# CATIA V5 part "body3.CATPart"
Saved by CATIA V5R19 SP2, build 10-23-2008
Part number: body3
Bounding box of the stored display mesh (mm): x -1290.464 to 1901.807, y -751.014 to 751.014, z 24.481 to 1015.966
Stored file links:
  C:\BEHROOZ\catia learning\tarh haye mashin\hb\body3.CATPart
  C:\BEHROOZ\catia learning\tarh haye mashin\hb\HB.CATPart
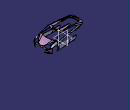
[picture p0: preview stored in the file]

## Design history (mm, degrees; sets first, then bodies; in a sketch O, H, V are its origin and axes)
Body1 (main body)
  Set1
    DatumSurface1
    DatumSurface2
    ThickSurface1: Surface DatumSurface2, TopOffset 1, BotOffset 0
    DatumSurface3 to DatumSurface6
    ThickSurface2: Surface DatumSurface6, TopOffset 1, BotOffset 0
    DatumSurface7 to DatumSurface9
    ThickSurface3: Surface DatumSurface9, TopOffset 1, BotOffset 0
    DatumSurface10 to DatumSurface12
    ThickSurface4: Surface DatumSurface12, TopOffset 1, BotOffset 0
    DatumSurface13
    DatumSurface14
    ThickSurface5: Surface DatumSurface14, TopOffset 1, BotOffset 0
    DatumSurface15
    ThickSurface6: Surface DatumSurface15, TopOffset 1, BotOffset 0
    DatumSurface16
    ThickSurface7: Surface DatumSurface16, TopOffset 1, BotOffset 0
    DatumSurface17
    ThickSurface8: Surface DatumSurface17, TopOffset 1, BotOffset 0
    DatumSurface18
    DatumSurface19
    ThickSurface9: Surface DatumSurface18, TopOffset 1, BotOffset 0
    DatumSurface20 to DatumSurface33
    ThickSurface10: Surface DatumSurface21, TopOffset 1, BotOffset 0
    ThickSurface11: Surface DatumSurface20, TopOffset 1, BotOffset 0
    ThickSurface12: Surface DatumSurface23, TopOffset 1, BotOffset 0
    ThickSurface13: Surface DatumSurface31, TopOffset 1, BotOffset 0
    ThickSurface14: Surface DatumSurface22, TopOffset 1, BotOffset 0
    ThickSurface15: Surface DatumSurface26, TopOffset 1, BotOffset 0
    ThickSurface16: Surface DatumSurface24, TopOffset 1, BotOffset 0
    ThickSurface17: Surface DatumSurface25, TopOffset 1, BotOffset 0
    ThickSurface18: Surface DatumSurface29, TopOffset 1, BotOffset 0
    ThickSurface19: Surface DatumSurface30, TopOffset 1, BotOffset 0
    ThickSurface20: Surface DatumSurface27, TopOffset 1, BotOffset 0
    ThickSurface21: Surface DatumSurface33, TopOffset 1, BotOffset 0
    DatumSurface34
    DatumSurface35
    ThickSurface22: Surface DatumSurface35, TopOffset 1, BotOffset 0
    DatumSurface36
    ThickSurface23: Surface DatumSurface36, TopOffset 1, BotOffset 0
    DatumSurface37
    DatumSurface38
    ThickSurface24: Surface DatumSurface38, TopOffset 1, BotOffset 0
    DatumSurface39 to DatumSurface53
    ThickSurface25: Surface DatumSurface52, TopOffset 1, BotOffset 0
    DatumSurface54
    ThickSurface26: Surface DatumSurface43, TopOffset 1, BotOffset 0
    DatumSurface55
    ThickSurface27: Surface DatumSurface55, TopOffset 1, BotOffset 0
    DatumSurface56
    DatumSurface57
    ThickSurface28: Surface DatumSurface57, TopOffset 1, BotOffset 0
    DatumSurface58
    ThickSurface29: Surface DatumSurface58, TopOffset 1, BotOffset 0
    DatumSurface59
    ThickSurface30: Surface DatumSurface59, TopOffset 1, BotOffset 0
    DatumSurface60
    ThickSurface31: Surface DatumSurface60, TopOffset 1, BotOffset 0
    DatumSurface61
    DatumSurface62
    ThickSurface32: Surface DatumSurface61, TopOffset 0, BotOffset 0.1
    DatumSurface63
    ThickSurface33: Surface DatumSurface63, TopOffset 1, BotOffset 1
    DatumSurface64
    ThickSurface34: Surface DatumSurface64, TopOffset 1, BotOffset 1
    ThickSurface35: Surface DatumSurface49, TopOffset 1, BotOffset 1
    ThickSurface36: Surface DatumSurface44, TopOffset 1, BotOffset 1
  ThickSurface37: Surface DatumSurface8, TopOffset 1, BotOffset 0
  Plane1: stored without definition
  ThickSurface38: Surface DatumSurface1, TopOffset 1, BotOffset 0
  Sketch1 on Plane1, origin (0, 750, 0), H (-1, 0, 0), V (0, 0, 1)
    arc A1 centre (186.8866, 85.6563) radius 1342.8585 from (-1152.0002, 188.8602) to (-1144.0658, -92.7661) ccw
    arc A2 centre (-1870.1711, 147.5694) radius 220.056 from (-1654.0237, 188.8602) to (-1721.0318, -14.2395) cw
  ThickSurface39: Surface DatumSurface34, TopOffset 1, BotOffset 0
  DatumSurface65
  ThickSurface40: Surface DatumSurface65, TopOffset 1, BotOffset 0
  ThickSurface41: Surface DatumSurface56, TopOffset 1, BotOffset 0
  DatumSurface66
  Plane2: stored without definition
  ThickSurface42: Surface DatumSurface53, TopOffset 1, BotOffset 0
  DatumCurve1
  DatumSurface67
  DatumCurve2
  Sketch2 on Plane2, origin (0, 750, 0), H (-1, 0, 0), V (0, 0, 1)
    line L1 (-1232.2927, 671.8812) -> (-1242.8283, 640.6061)
    arc A1 centre (899.321, -4723.5379) radius 5776.0579 from (-1242.8283, 640.6061) to (-1596.8305, 485.3077) ccw
    arc A2 centre (-3138.2001, 32.1539) radius 2082.7095 from (-1151.2818, 656.5214) to (-1055.4907, 32.8832) cw
    line L2 (-1055.4907, 32.8832) -> (-177.5083, 73.2965)
    arc A3 centre (-4224.993, 1613.9757) radius 4330.7996 from (-177.5083, 73.2965) to (64.8416, 1019.7164) ccw
    projected line E1 (-1296.9049, 618.7198) -> (-1295.6556, 619.207) from edge [face of ThickSurface39 | face of ThickSurface41]
    line L3 (-1232.2927, 671.8812) -> (-1214.6725, 696.6608)
  Pocket1: profile Sketch2, direction (0, 1, 0), length 281, opposite side length 1796, thin wall 1
  DatumCurve3
  DatumCurve4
